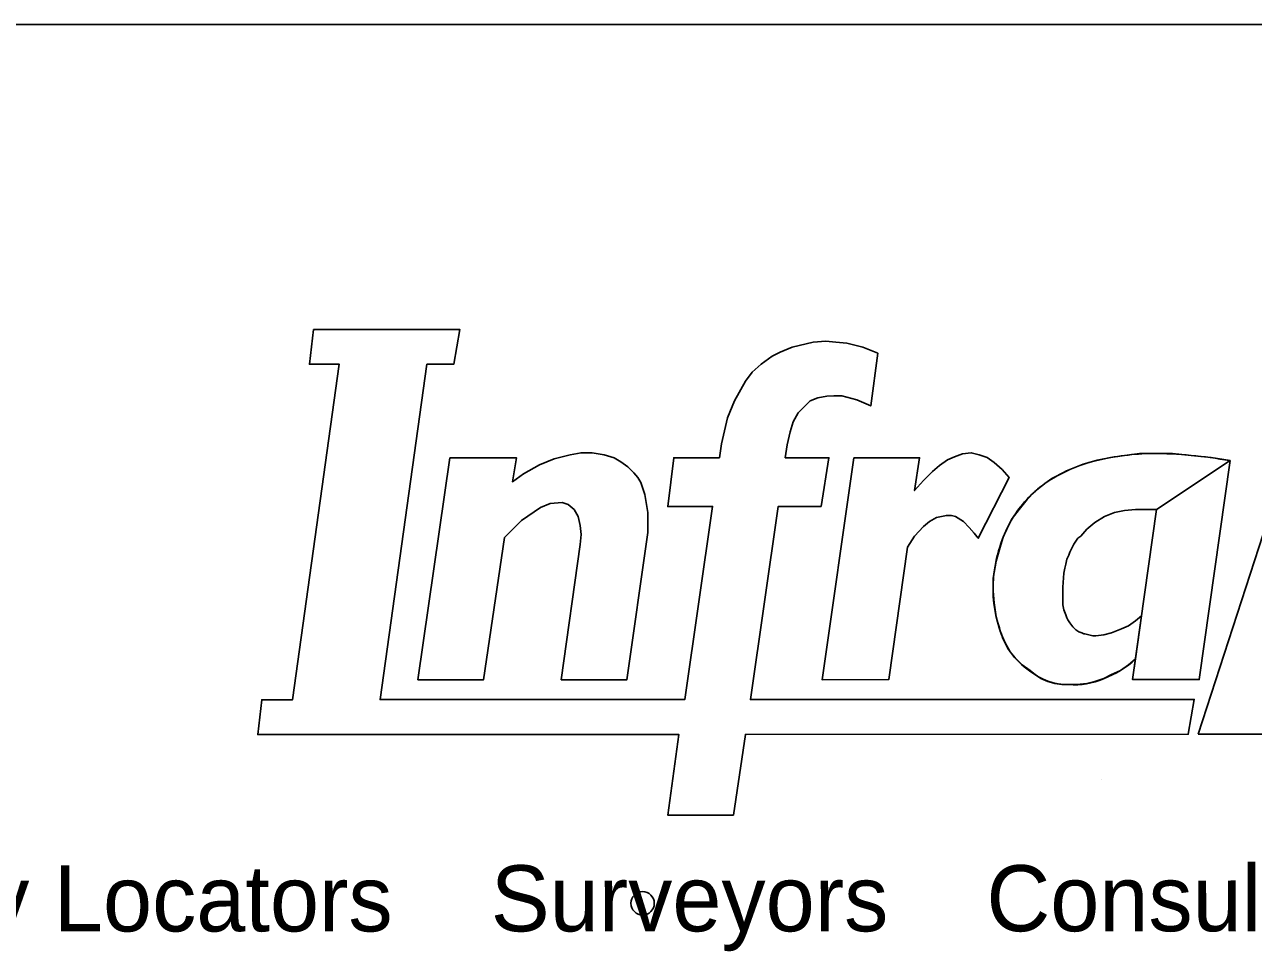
# Model space of a CAD drawing. Extents: x 2158280 to 2158980, y 1040586 to 1041166.
# Drawn here: x 2158604.75 to 2158641.79, y 1040689.71 to 1040717.65 of the extents above; entities that cross this region are included whole.
import ezdxf

# ---------------------------------------------------------------- set-up
doc = ezdxf.new("R2010")
doc.units = 0
doc.layers.add('SHT_B_Grid-Major-Line', color=7, linetype='Continuous')
doc.layers.add('SHT_B_North-Arrow', color=7, linetype='Continuous')

msp = doc.modelspace()

# ---------------------------------------------------------------- linework, layer by layer
at = {"layer": 'SHT_B_Grid-Major-Line'}
msp.add_line((2158638.145, 1040697.902), (2158638.235, 1040698.532), dxfattribs=at)
msp.add_line((2158638.145, 1040697.902), (2158638.235, 1040698.532), dxfattribs=at)
for points in [[(2158613.453, 1040708.457), (2158617.863, 1040708.458), (2158617.683, 1040707.408), (2158616.873, 1040707.408), (2158615.465, 1040697.298), (2158624.645, 1040697.3), (2158625.484, 1040703.12), (2158624.134, 1040703.119), (2158624.314, 1040704.589), (2158625.694, 1040704.59), (2158625.754, 1040705.01), (2158625.933, 1040705.79), (2158626.143, 1040706.3), (2158626.473, 1040706.9), (2158626.683, 1040707.17), (2158626.953, 1040707.41), (2158627.283, 1040707.65), (2158627.523, 1040707.77), (2158627.883, 1040707.92), (2158628.513, 1040708.07), (2158628.903, 1040708.1), (2158629.203, 1040708.071), (2158629.533, 1040708.041), (2158629.893, 1040707.951), (2158630.013, 1040707.921), (2158630.463, 1040707.741), (2158630.253, 1040706.151), (2158629.833, 1040706.331), (2158629.383, 1040706.451), (2158629.143, 1040706.451), (2158628.933, 1040706.45), (2158628.663, 1040706.39), (2158628.423, 1040706.3), (2158628.243, 1040706.12), (2158628.063, 1040705.94), (2158627.913, 1040705.67), (2158627.823, 1040705.37), (2158627.734, 1040704.98), (2158627.674, 1040704.59), (2158628.994, 1040704.591), (2158628.754, 1040703.12), (2158627.464, 1040703.12), (2158626.625, 1040697.3), (2158640.005, 1040697.303), (2158639.825, 1040696.253), (2158626.475, 1040696.25), (2158626.116, 1040693.82), (2158624.136, 1040693.819), (2158624.465, 1040696.25), (2158611.775, 1040696.247), (2158611.895, 1040697.297), (2158612.825, 1040697.297), (2158614.233, 1040707.407), (2158613.333, 1040707.407)], [(2158613.453, 1040708.457), (2158617.863, 1040708.458), (2158617.683, 1040707.408), (2158616.873, 1040707.408), (2158615.465, 1040697.298), (2158624.645, 1040697.3), (2158625.484, 1040703.12), (2158624.134, 1040703.119), (2158624.314, 1040704.589), (2158625.694, 1040704.59), (2158625.754, 1040705.01), (2158625.933, 1040705.79), (2158626.143, 1040706.3), (2158626.473, 1040706.9), (2158626.683, 1040707.17), (2158626.953, 1040707.41), (2158627.283, 1040707.65), (2158627.523, 1040707.77), (2158627.883, 1040707.92), (2158628.513, 1040708.07), (2158628.903, 1040708.1), (2158629.203, 1040708.071), (2158629.533, 1040708.041), (2158629.893, 1040707.951), (2158630.013, 1040707.921), (2158630.463, 1040707.741), (2158630.253, 1040706.151), (2158629.833, 1040706.331), (2158629.383, 1040706.451), (2158629.143, 1040706.451), (2158628.933, 1040706.45), (2158628.663, 1040706.39), (2158628.423, 1040706.3), (2158628.243, 1040706.12), (2158628.063, 1040705.94), (2158627.913, 1040705.67), (2158627.823, 1040705.37), (2158627.734, 1040704.98), (2158627.674, 1040704.59), (2158628.994, 1040704.591), (2158628.754, 1040703.12), (2158627.464, 1040703.12), (2158626.625, 1040697.3), (2158640.005, 1040697.303), (2158639.825, 1040696.253), (2158626.475, 1040696.25), (2158626.116, 1040693.82), (2158624.136, 1040693.819), (2158624.465, 1040696.25), (2158611.775, 1040696.247), (2158611.895, 1040697.297), (2158612.825, 1040697.297), (2158614.233, 1040707.407), (2158613.333, 1040707.407)], [(2158640.125, 1040696.253), (2158642.315, 1040696.253), (2158644.504, 1040702.944), (2158646.155, 1040696.254), (2158647.595, 1040696.255), (2158651.134, 1040702.705), (2158651.525, 1040696.255), (2158653.595, 1040696.256), (2158652.993, 1040706.306), (2158650.743, 1040706.305), (2158647.325, 1040700.094), (2158645.793, 1040706.304), (2158643.393, 1040706.304)], [(2158640.125, 1040696.253), (2158642.315, 1040696.253), (2158644.504, 1040702.944), (2158646.155, 1040696.254), (2158647.595, 1040696.255), (2158651.134, 1040702.705), (2158651.525, 1040696.255), (2158653.595, 1040696.256), (2158652.993, 1040706.306), (2158650.743, 1040706.305), (2158647.325, 1040700.094), (2158645.793, 1040706.304), (2158643.393, 1040706.304)], [(2158617.564, 1040704.588), (2158619.574, 1040704.588), (2158619.454, 1040703.868), (2158619.784, 1040704.109), (2158620.264, 1040704.379), (2158620.714, 1040704.559), (2158621.194, 1040704.679), (2158621.524, 1040704.739), (2158621.854, 1040704.739), (2158622.214, 1040704.679), (2158622.514, 1040704.589), (2158622.724, 1040704.469), (2158622.934, 1040704.319), (2158623.114, 1040704.139), (2158623.234, 1040703.989), (2158623.324, 1040703.839), (2158623.384, 1040703.659), (2158623.444, 1040703.479), (2158623.534, 1040702.939), (2158623.534, 1040702.339), (2158622.905, 1040697.899), (2158620.925, 1040697.899), (2158621.494, 1040701.979), (2158621.524, 1040702.279), (2158621.494, 1040702.549), (2158621.434, 1040702.819), (2158621.314, 1040703.029), (2158621.134, 1040703.179), (2158620.954, 1040703.239), (2158620.594, 1040703.209), (2158620.294, 1040703.089), (2158619.724, 1040702.699), (2158619.214, 1040702.188), (2158618.585, 1040697.898), (2158616.605, 1040697.898)], [(2158617.564, 1040704.588), (2158619.574, 1040704.588), (2158619.454, 1040703.868), (2158619.784, 1040704.109), (2158620.264, 1040704.379), (2158620.714, 1040704.559), (2158621.194, 1040704.679), (2158621.524, 1040704.739), (2158621.854, 1040704.739), (2158622.214, 1040704.679), (2158622.514, 1040704.589), (2158622.724, 1040704.469), (2158622.934, 1040704.319), (2158623.114, 1040704.139), (2158623.234, 1040703.989), (2158623.324, 1040703.839), (2158623.384, 1040703.659), (2158623.444, 1040703.479), (2158623.534, 1040702.939), (2158623.534, 1040702.339), (2158622.905, 1040697.899), (2158620.925, 1040697.899), (2158621.494, 1040701.979), (2158621.524, 1040702.279), (2158621.494, 1040702.549), (2158621.434, 1040702.819), (2158621.314, 1040703.029), (2158621.134, 1040703.179), (2158620.954, 1040703.239), (2158620.594, 1040703.209), (2158620.294, 1040703.089), (2158619.724, 1040702.699), (2158619.214, 1040702.188), (2158618.585, 1040697.898), (2158616.605, 1040697.898)], [(2158629.744, 1040704.591), (2158631.724, 1040704.591), (2158631.574, 1040703.601), (2158631.844, 1040703.901), (2158632.114, 1040704.171), (2158632.324, 1040704.351), (2158632.564, 1040704.531), (2158632.774, 1040704.621), (2158633.014, 1040704.711), (2158633.284, 1040704.741), (2158633.524, 1040704.681), (2158633.764, 1040704.592), (2158633.974, 1040704.442), (2158634.214, 1040704.232), (2158634.424, 1040703.992), (2158633.494, 1040702.161), (2158633.374, 1040702.311), (2158633.224, 1040702.491), (2158633.044, 1040702.671), (2158632.804, 1040702.821), (2158632.684, 1040702.851), (2158632.534, 1040702.851), (2158632.384, 1040702.821), (2158632.234, 1040702.791), (2158632.024, 1040702.671), (2158631.844, 1040702.521), (2158631.574, 1040702.221), (2158631.364, 1040701.891), (2158630.795, 1040697.901), (2158628.785, 1040697.9)], [(2158629.744, 1040704.591), (2158631.724, 1040704.591), (2158631.574, 1040703.601), (2158631.844, 1040703.901), (2158632.114, 1040704.171), (2158632.324, 1040704.351), (2158632.564, 1040704.531), (2158632.774, 1040704.621), (2158633.014, 1040704.711), (2158633.284, 1040704.741), (2158633.524, 1040704.681), (2158633.764, 1040704.592), (2158633.974, 1040704.442), (2158634.214, 1040704.232), (2158634.424, 1040703.992), (2158633.494, 1040702.161), (2158633.374, 1040702.311), (2158633.224, 1040702.491), (2158633.044, 1040702.671), (2158632.804, 1040702.821), (2158632.684, 1040702.851), (2158632.534, 1040702.851), (2158632.384, 1040702.821), (2158632.234, 1040702.791), (2158632.024, 1040702.671), (2158631.844, 1040702.521), (2158631.574, 1040702.221), (2158631.364, 1040701.891), (2158630.795, 1040697.901), (2158628.785, 1040697.9)], [(2158638.864, 1040703.033), (2158641.084, 1040704.503), (2158640.155, 1040697.903), (2158638.145, 1040697.902)], [(2158638.864, 1040703.033), (2158641.084, 1040704.503), (2158640.155, 1040697.903), (2158638.145, 1040697.902)]]:
    msp.add_lwpolyline(points, close=True, dxfattribs=at)
for points in [[(2158638.864, 1040703.033), (2158641.084, 1040704.503), (2158640.514, 1040704.593), (2158639.914, 1040704.653), (2158639.344, 1040704.713), (2158638.744, 1040704.713), (2158638.354, 1040704.713), (2158637.904, 1040704.652), (2158637.484, 1040704.592), (2158637.064, 1040704.502), (2158636.824, 1040704.442), (2158636.554, 1040704.352), (2158636.254, 1040704.232), (2158635.954, 1040704.082), (2158635.714, 1040703.962), (2158635.504, 1040703.812), (2158635.204, 1040703.572), (2158634.964, 1040703.332), (2158634.724, 1040703.032), (2158634.514, 1040702.762), (2158634.364, 1040702.462), (2158634.244, 1040702.192), (2158634.154, 1040701.892), (2158634.034, 1040701.472), (2158633.944, 1040700.962), (2158633.945, 1040700.572), (2158633.975, 1040700.212), (2158634.035, 1040699.792), (2158634.125, 1040699.462), (2158634.185, 1040699.282), (2158634.305, 1040699.012), (2158634.455, 1040698.742), (2158634.605, 1040698.562), (2158634.815, 1040698.352), (2158635.055, 1040698.172), (2158635.205, 1040698.052), (2158635.385, 1040697.932), (2158635.595, 1040697.842), (2158635.805, 1040697.782), (2158636.015, 1040697.752), (2158636.225, 1040697.752), (2158636.465, 1040697.752), (2158636.765, 1040697.782), (2158637.005, 1040697.842), (2158637.275, 1040697.932), (2158637.515, 1040698.052), (2158637.785, 1040698.172), (2158638.025, 1040698.352), (2158638.235, 1040698.532), (2158638.415, 1040699.823), (2158638.235, 1040699.672), (2158638.025, 1040699.522), (2158637.815, 1040699.432), (2158637.665, 1040699.372), (2158637.515, 1040699.312), (2158637.275, 1040699.252), (2158637.035, 1040699.222), (2158636.945, 1040699.222), (2158636.825, 1040699.252), (2158636.705, 1040699.282), (2158636.675, 1040699.282), (2158636.615, 1040699.312), (2158636.525, 1040699.342), (2158636.435, 1040699.402), (2158636.345, 1040699.492)], [(2158638.864, 1040703.033), (2158641.084, 1040704.503), (2158640.514, 1040704.593), (2158639.914, 1040704.653), (2158639.344, 1040704.713), (2158638.744, 1040704.713), (2158638.354, 1040704.713), (2158637.904, 1040704.652), (2158637.484, 1040704.592), (2158637.064, 1040704.502), (2158636.824, 1040704.442), (2158636.554, 1040704.352), (2158636.254, 1040704.232), (2158635.954, 1040704.082), (2158635.714, 1040703.962), (2158635.504, 1040703.812), (2158635.204, 1040703.572), (2158634.964, 1040703.332), (2158634.724, 1040703.032), (2158634.514, 1040702.762), (2158634.364, 1040702.462), (2158634.244, 1040702.192), (2158634.154, 1040701.892), (2158634.034, 1040701.472), (2158633.944, 1040700.962), (2158633.945, 1040700.572), (2158633.975, 1040700.212), (2158634.035, 1040699.792), (2158634.125, 1040699.462), (2158634.185, 1040699.282), (2158634.305, 1040699.012), (2158634.455, 1040698.742), (2158634.605, 1040698.562), (2158634.815, 1040698.352), (2158635.055, 1040698.172), (2158635.205, 1040698.052), (2158635.385, 1040697.932), (2158635.595, 1040697.842), (2158635.805, 1040697.782), (2158636.015, 1040697.752), (2158636.225, 1040697.752), (2158636.465, 1040697.752), (2158636.765, 1040697.782), (2158637.005, 1040697.842), (2158637.275, 1040697.932), (2158637.515, 1040698.052), (2158637.785, 1040698.172), (2158638.025, 1040698.352), (2158638.235, 1040698.532), (2158638.415, 1040699.823), (2158638.235, 1040699.672), (2158638.025, 1040699.522), (2158637.815, 1040699.432), (2158637.665, 1040699.372), (2158637.515, 1040699.312), (2158637.275, 1040699.252), (2158637.035, 1040699.222), (2158636.945, 1040699.222), (2158636.825, 1040699.252), (2158636.705, 1040699.282), (2158636.675, 1040699.282), (2158636.615, 1040699.312), (2158636.525, 1040699.342), (2158636.435, 1040699.402), (2158636.345, 1040699.492)], [(2158641.084, 1040704.503), (2158640.155, 1040697.903), (2158638.145, 1040697.902), (2158640.155, 1040697.903)], [(2158641.084, 1040704.503), (2158640.155, 1040697.903), (2158638.145, 1040697.902), (2158640.155, 1040697.903)], [(2158636.345, 1040699.492), (2158636.255, 1040699.612), (2158636.195, 1040699.702), (2158636.165, 1040699.762), (2158636.135, 1040699.852), (2158636.075, 1040700.002), (2158636.045, 1040700.152), (2158636.045, 1040700.242), (2158636.045, 1040700.692), (2158636.074, 1040701.112), (2158636.104, 1040701.262), (2158636.134, 1040701.382), (2158636.164, 1040701.532), (2158636.224, 1040701.652), (2158636.254, 1040701.742), (2158636.284, 1040701.802), (2158636.314, 1040701.862), (2158636.374, 1040701.982), (2158636.434, 1040702.072), (2158636.494, 1040702.162), (2158636.584, 1040702.222), (2158636.764, 1040702.432), (2158637.004, 1040702.642), (2158637.304, 1040702.822), (2158637.604, 1040702.942), (2158637.904, 1040703.002), (2158638.234, 1040703.032), (2158638.864, 1040703.033)], [(2158636.345, 1040699.492), (2158636.255, 1040699.612), (2158636.195, 1040699.702), (2158636.165, 1040699.762), (2158636.135, 1040699.852), (2158636.075, 1040700.002), (2158636.045, 1040700.152), (2158636.045, 1040700.242), (2158636.045, 1040700.692), (2158636.074, 1040701.112), (2158636.104, 1040701.262), (2158636.134, 1040701.382), (2158636.164, 1040701.532), (2158636.224, 1040701.652), (2158636.254, 1040701.742), (2158636.284, 1040701.802), (2158636.314, 1040701.862), (2158636.374, 1040701.982), (2158636.434, 1040702.072), (2158636.494, 1040702.162), (2158636.584, 1040702.222), (2158636.764, 1040702.432), (2158637.004, 1040702.642), (2158637.304, 1040702.822), (2158637.604, 1040702.942), (2158637.904, 1040703.002), (2158638.234, 1040703.032), (2158638.864, 1040703.033)]]:
    msp.add_lwpolyline(points, dxfattribs=at)
msp.add_circle((2158623.377, 1040691.159), 0.352, dxfattribs=at)
msp.add_circle((2158623.377, 1040691.159), 0.352, dxfattribs=at)
for centre, radius, start, end in [((2158638.946, 1040696.348), 8.376, 91.3825, 102.8864), ((2158638.946, 1040696.348), 8.376, 91.3825, 102.8864), ((2158638.579, 1040690.551), 14.171, 79.8949, 89.333), ((2158638.579, 1040690.551), 14.171, 79.8949, 89.333), ((2158638.132, 1040700.017), 4.617, 103.1881, 124.7438), ((2158638.132, 1040700.017), 4.617, 103.1881, 124.7438), ((2158637.594, 1040700.88), 3.602, 125.534, 148.7543), ((2158637.594, 1040700.88), 3.602, 125.534, 148.7543), ((2158638.371, 1040700.559), 4.435, 150.4218, 174.6396), ((2158638.371, 1040700.559), 4.435, 150.4218, 174.6396), ((2158637.585, 1040700.629), 3.646, 174.5811, 198.676), ((2158637.585, 1040700.629), 3.646, 174.5811, 198.676), ((2158636.266, 1040699.998), 2.201, 194.1052, 236.1864), ((2158636.266, 1040699.998), 2.201, 194.1052, 236.1864), ((2158636.241, 1040700.696), 2.951, 290.3221, 312.6068), ((2158636.241, 1040700.696), 2.951, 290.3221, 312.6068), ((2158636.185, 1040699.532), 1.779, 229.9908, 271.2799), ((2158636.185, 1040699.532), 1.779, 229.9908, 271.2799), ((2158636.408, 1040699.842), 2.096, 264.984, 294.153), ((2158636.408, 1040699.842), 2.096, 264.984, 294.153)]:
    msp.add_arc(centre, radius, start, end, dxfattribs=at)
at = {"layer": 'SHT_B_North-Arrow'}
for p, q in [((2158349.565, 1040717.645), (2158969.565, 1040717.645)), ((2158637.205, 1040694.885), (2158637.205, 1040694.885)), ((2158637.205, 1040694.885), (2158637.205, 1040694.885))]:
    msp.add_line(p, q, dxfattribs=at)

# ---------------------------------------------------------------- texts
at = {"layer": 'SHT_B_Grid-Major-Line'}
msp.add_text('Utility Locators    Surveyors    Consulting Engineers', height=1.9908, rotation=0.0124, dxfattribs=at).set_placement((2158598.383, 1040690.309))
msp.add_text('Utility Locators    Surveyors    Consulting Engineers', height=1.9908, rotation=0.0124, dxfattribs=at).set_placement((2158598.383, 1040690.309))

doc.saveas('drawing.dxf')
